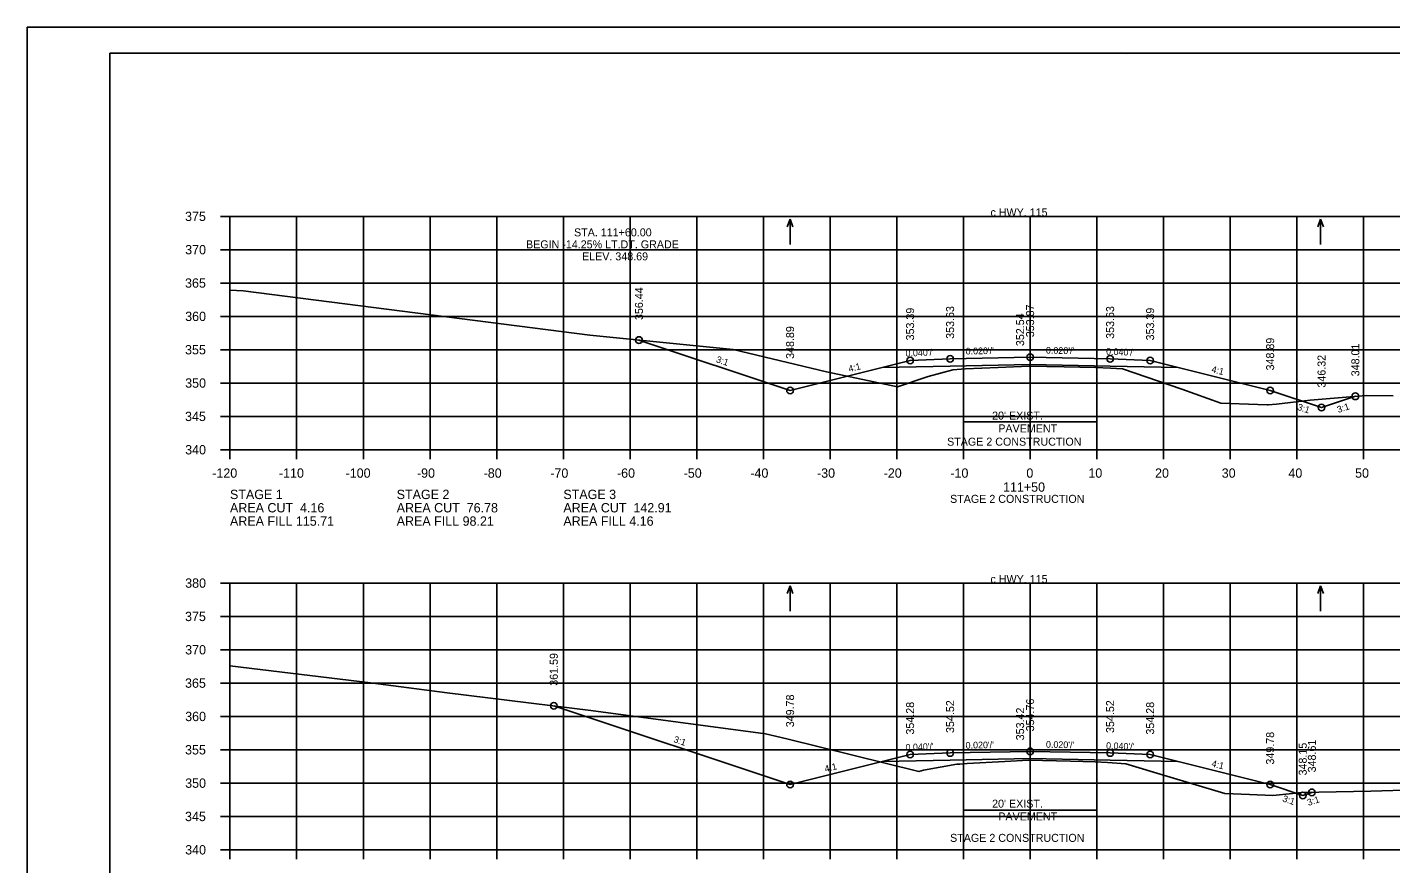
# Model space of a CAD drawing. Extents: x 1630712 to 1632516, y 782146 to 785403.
# Drawn here: x 1632182.6 to 1632387, y 784424.5 to 784550 of the extents above; entities that cross this region are included whole.
import ezdxf

# ---------------------------------------------------------------- set-up
doc = ezdxf.new("R2010")
doc.units = 0
for name, color, linetype in [('Notes', 7, 'Continuous'), ('R_Alt Surface', 7, 'Continuous'), ('R_Axis', 7, 'Continuous'), ('R_Axis Annot', 7, 'Continuous'), ('R_Border', 7, 'Continuous'), ('R_Exist Surface', 7, 'Continuous'), ('R_Fin Surface', 7, 'Continuous'), ('R_Grid', 7, 'Continuous'), ('R_No Plot', 7, 'Continuous'), ('R_Water Annot', 7, 'Continuous'), ('R_Xsect Elev', 7, 'Continuous'), ('R_Xsect Slope', 7, 'Continuous')]:
    doc.layers.add(name, color=color, linetype=linetype)

msp = doc.modelspace()

# ---------------------------------------------------------------- linework, layer by layer
at = {"layer": 'Notes'}
for p, q in [((1632322.96, 784489.09), (1632322.96, 784492.49)), ((1632322.96, 784490.79), (1632342.96, 784490.79)), ((1632342.96, 784489.09), (1632342.96, 784492.49)), ((1632322.96, 784430.89), (1632322.96, 784434.29)), ((1632342.96, 784430.89), (1632342.96, 784434.29)), ((1632322.96, 784432.59), (1632342.96, 784432.59))]:
    msp.add_line(p, q, dxfattribs=at)
at = {"layer": 'R_Alt Surface'}
for points in [[(1632310.78, 784498.97), (1632320.96, 784499.18), (1632332.96, 784499.42), (1632344.96, 784499.18), (1632355.15, 784498.97)], [(1632310.78, 784439.86), (1632320.96, 784440.07), (1632332.96, 784440.31), (1632344.96, 784440.07), (1632355.15, 784439.86)]]:
    msp.add_lwpolyline(points, dxfattribs=at)
at = {"layer": 'R_Axis'}
for p, q in [((1632211.56, 784521.63), (1632212.96, 784521.63)), ((1632212.96, 784486.63), (1632212.96, 784521.63)), ((1632211.56, 784516.63), (1632212.96, 784516.63)), ((1632211.56, 784511.63), (1632212.96, 784511.63)), ((1632211.56, 784506.63), (1632212.96, 784506.63)), ((1632211.56, 784501.63), (1632212.96, 784501.63)), ((1632211.56, 784496.63), (1632212.96, 784496.63)), ((1632211.56, 784491.63), (1632212.96, 784491.63)), ((1632211.56, 784486.63), (1632212.96, 784486.63)), ((1632212.96, 784486.63), (1632492.96, 784486.63)), ((1632212.96, 784485.23), (1632212.96, 784486.63)), ((1632222.96, 784485.23), (1632222.96, 784486.63)), ((1632232.96, 784485.23), (1632232.96, 784486.63)), ((1632242.96, 784485.23), (1632242.96, 784486.63)), ((1632252.96, 784485.23), (1632252.96, 784486.63)), ((1632262.96, 784485.23), (1632262.96, 784486.63)), ((1632272.96, 784485.23), (1632272.96, 784486.63)), ((1632282.96, 784485.23), (1632282.96, 784486.63)), ((1632292.96, 784485.23), (1632292.96, 784486.63)), ((1632302.96, 784485.23), (1632302.96, 784486.63)), ((1632312.96, 784485.23), (1632312.96, 784486.63)), ((1632322.96, 784485.23), (1632322.96, 784486.63)), ((1632332.96, 784485.23), (1632332.96, 784486.63)), ((1632342.96, 784485.23), (1632342.96, 784486.63)), ((1632352.96, 784485.23), (1632352.96, 784486.63)), ((1632362.96, 784485.23), (1632362.96, 784486.63)), ((1632372.96, 784485.23), (1632372.96, 784486.63)), ((1632382.96, 784485.23), (1632382.96, 784486.63)), ((1632211.56, 784466.63), (1632212.96, 784466.63)), ((1632212.96, 784426.63), (1632212.96, 784466.63)), ((1632211.56, 784461.63), (1632212.96, 784461.63)), ((1632211.56, 784456.63), (1632212.96, 784456.63)), ((1632211.56, 784451.63), (1632212.96, 784451.63)), ((1632211.56, 784446.63), (1632212.96, 784446.63)), ((1632211.56, 784441.63), (1632212.96, 784441.63)), ((1632211.56, 784436.63), (1632212.96, 784436.63)), ((1632211.56, 784431.63), (1632212.96, 784431.63)), ((1632211.56, 784426.63), (1632212.96, 784426.63)), ((1632212.96, 784426.63), (1632492.96, 784426.63)), ((1632212.96, 784425.23), (1632212.96, 784426.63)), ((1632222.96, 784425.23), (1632222.96, 784426.63)), ((1632232.96, 784425.23), (1632232.96, 784426.63)), ((1632242.96, 784425.23), (1632242.96, 784426.63)), ((1632252.96, 784425.23), (1632252.96, 784426.63)), ((1632262.96, 784425.23), (1632262.96, 784426.63)), ((1632272.96, 784425.23), (1632272.96, 784426.63)), ((1632282.96, 784425.23), (1632282.96, 784426.63)), ((1632292.96, 784425.23), (1632292.96, 784426.63)), ((1632302.96, 784425.23), (1632302.96, 784426.63)), ((1632312.96, 784425.23), (1632312.96, 784426.63)), ((1632322.96, 784425.23), (1632322.96, 784426.63)), ((1632332.96, 784425.23), (1632332.96, 784426.63)), ((1632342.96, 784425.23), (1632342.96, 784426.63)), ((1632352.96, 784425.23), (1632352.96, 784426.63)), ((1632362.96, 784425.23), (1632362.96, 784426.63)), ((1632372.96, 784425.23), (1632372.96, 784426.63)), ((1632382.96, 784425.23), (1632382.96, 784426.63))]:
    msp.add_line(p, q, dxfattribs=at)
at = {"layer": 'R_Border'}
for p, q in [((1632194.96, 784546.09), (1632511.14, 784546.09)), ((1632194.96, 784340.63), (1632194.96, 784546.09)), ((1632347.48, 784545.83), (1632347.48, 784545.83)), ((1632347.48, 784545.83), (1632347.48, 784545.83))]:
    msp.add_line(p, q, dxfattribs=at)
at = {"layer": 'R_Exist Surface'}
for points in [[(1632212.96, 784510.58), (1632214.92, 784510.44), (1632266.95, 784503.82), (1632288.42, 784501.64), (1632302.44, 784498.29), (1632313.05, 784496.07), (1632317.69, 784497.6), (1632321.36, 784498.59), (1632322.61, 784498.72), (1632323.29, 784498.77), (1632328.17, 784498.98), (1632332.8, 784499.17), (1632338.09, 784499.07), (1632342.77, 784498.98), (1632345.04, 784498.86), (1632346.8, 784498.78), (1632355.7, 784495.71), (1632361.57, 784493.59), (1632367.11, 784493.41), (1632368.51, 784493.37), (1632368.65, 784493.37), (1632369.92, 784493.47), (1632374.95, 784494.07), (1632383.37, 784494.78), (1632387.42, 784494.7)], [(1632212.96, 784454.2), (1632234.02, 784451.68), (1632245.51, 784450.19), (1632267.07, 784447.54), (1632293.29, 784444), (1632296.45, 784443.29), (1632316.27, 784438.39), (1632316.99, 784438.55), (1632321.99, 784439.45), (1632322.41, 784439.48), (1632323.53, 784439.59), (1632329.19, 784439.88), (1632332.7, 784440.05), (1632339.02, 784439.91), (1632342.72, 784439.83), (1632344.58, 784439.72), (1632347.31, 784439.53), (1632353.47, 784437.67), (1632362.15, 784435.06), (1632365.87, 784434.93), (1632369.38, 784434.78), (1632372.3, 784435.08), (1632373.68, 784435.21), (1632384.07, 784435.42), (1632397.36, 784435.83)]]:
    msp.add_lwpolyline(points, dxfattribs=at)
at = {"layer": 'R_Fin Surface'}
for points in [[(1632274.3, 784503.08), (1632296.96, 784495.52), (1632310.78, 784498.97), (1632314.96, 784500.02), (1632320.96, 784500.26), (1632332.96, 784500.5), (1632344.96, 784500.26), (1632350.96, 784500.02), (1632355.15, 784498.97), (1632368.96, 784495.52), (1632376.67, 784492.95), (1632381.74, 784494.64)], [(1632261.52, 784448.23), (1632296.96, 784436.41), (1632310.78, 784439.86), (1632314.96, 784440.91), (1632320.96, 784441.15), (1632332.96, 784441.39), (1632344.96, 784441.15), (1632350.96, 784440.91), (1632355.15, 784439.86), (1632368.96, 784436.41), (1632373.85, 784434.78), (1632375.22, 784435.24)]]:
    msp.add_lwpolyline(points, dxfattribs=at)
at = {"layer": 'R_Grid'}
for p, q in [((1632212.96, 784521.63), (1632492.96, 784521.63)), ((1632212.96, 784486.63), (1632212.96, 784521.63)), ((1632222.96, 784486.63), (1632222.96, 784521.63)), ((1632232.96, 784486.63), (1632232.96, 784521.63)), ((1632242.96, 784486.63), (1632242.96, 784521.63)), ((1632252.96, 784486.63), (1632252.96, 784521.63)), ((1632262.96, 784486.63), (1632262.96, 784521.63)), ((1632272.96, 784486.63), (1632272.96, 784521.63)), ((1632282.96, 784486.63), (1632282.96, 784521.63)), ((1632292.96, 784486.63), (1632292.96, 784521.63)), ((1632302.96, 784486.63), (1632302.96, 784521.63)), ((1632312.96, 784486.63), (1632312.96, 784521.63)), ((1632322.96, 784486.63), (1632322.96, 784521.63)), ((1632332.96, 784486.63), (1632332.96, 784521.63)), ((1632342.96, 784486.63), (1632342.96, 784521.63)), ((1632352.96, 784486.63), (1632352.96, 784521.63)), ((1632362.96, 784486.63), (1632362.96, 784521.63)), ((1632372.96, 784486.63), (1632372.96, 784521.63)), ((1632382.96, 784486.63), (1632382.96, 784521.63)), ((1632212.96, 784516.63), (1632492.96, 784516.63)), ((1632212.96, 784511.63), (1632492.96, 784511.63)), ((1632212.96, 784506.63), (1632492.96, 784506.63)), ((1632212.96, 784501.63), (1632492.96, 784501.63)), ((1632212.96, 784496.63), (1632492.96, 784496.63)), ((1632212.96, 784491.63), (1632492.96, 784491.63)), ((1632212.96, 784486.63), (1632492.96, 784486.63)), ((1632212.96, 784466.63), (1632492.96, 784466.63)), ((1632212.96, 784426.63), (1632212.96, 784466.63)), ((1632222.96, 784426.63), (1632222.96, 784466.63)), ((1632232.96, 784426.63), (1632232.96, 784466.63)), ((1632242.96, 784426.63), (1632242.96, 784466.63)), ((1632252.96, 784426.63), (1632252.96, 784466.63)), ((1632262.96, 784426.63), (1632262.96, 784466.63)), ((1632272.96, 784426.63), (1632272.96, 784466.63)), ((1632282.96, 784426.63), (1632282.96, 784466.63)), ((1632292.96, 784426.63), (1632292.96, 784466.63)), ((1632302.96, 784426.63), (1632302.96, 784466.63)), ((1632312.96, 784426.63), (1632312.96, 784466.63)), ((1632322.96, 784426.63), (1632322.96, 784466.63)), ((1632332.96, 784426.63), (1632332.96, 784466.63)), ((1632342.96, 784426.63), (1632342.96, 784466.63)), ((1632352.96, 784426.63), (1632352.96, 784466.63)), ((1632362.96, 784426.63), (1632362.96, 784466.63)), ((1632372.96, 784426.63), (1632372.96, 784466.63)), ((1632382.96, 784426.63), (1632382.96, 784466.63)), ((1632212.96, 784461.63), (1632492.96, 784461.63)), ((1632212.96, 784456.63), (1632492.96, 784456.63)), ((1632212.96, 784451.63), (1632492.96, 784451.63)), ((1632212.96, 784446.63), (1632492.96, 784446.63)), ((1632212.96, 784441.63), (1632492.96, 784441.63)), ((1632212.96, 784436.63), (1632492.96, 784436.63)), ((1632212.96, 784431.63), (1632492.96, 784431.63)), ((1632212.96, 784426.63), (1632492.96, 784426.63))]:
    msp.add_line(p, q, dxfattribs=at)
at = {"layer": 'R_No Plot'}
msp.add_line((1632182.56, 784549.99), (1632515.9, 784549.99), dxfattribs=at)
msp.add_lwpolyline([(1632182.56, 784549.99), (1632515.9, 784549.99), (1632515.9, 784336.65), (1632182.56, 784336.65)], close=True, dxfattribs=at)
for centre in [(1632274.3, 784503.08), (1632320.96, 784500.26), (1632332.96, 784500.5), (1632344.96, 784500.26), (1632314.96, 784500.02), (1632350.96, 784500.02), (1632296.96, 784495.52), (1632296.96, 784495.52), (1632368.96, 784495.52), (1632381.74, 784494.64), (1632376.67, 784492.95), (1632261.52, 784448.23), (1632320.96, 784441.15), (1632332.96, 784441.39), (1632344.96, 784441.15), (1632314.96, 784440.91), (1632350.96, 784440.91), (1632296.96, 784436.41), (1632296.96, 784436.41), (1632368.96, 784436.41), (1632375.22, 784435.24), (1632373.85, 784434.78)]:
    msp.add_circle(centre, 0.5, dxfattribs=at)
at = {"layer": 'R_Water Annot'}
for p, q in [((1632296.96, 784521.2), (1632296.54, 784520.05)), ((1632296.96, 784517.43), (1632296.96, 784521.2)), ((1632296.96, 784521.2), (1632297.38, 784520.05)), ((1632376.53, 784521.2), (1632376.11, 784520.05)), ((1632376.53, 784517.43), (1632376.53, 784521.2)), ((1632376.53, 784521.2), (1632376.95, 784520.05)), ((1632296.96, 784466.2), (1632296.54, 784465.05)), ((1632296.96, 784462.43), (1632296.96, 784466.2)), ((1632296.96, 784466.2), (1632297.38, 784465.05)), ((1632376.53, 784466.2), (1632376.11, 784465.05)), ((1632376.53, 784462.43), (1632376.53, 784466.2)), ((1632376.53, 784466.2), (1632376.95, 784465.05))]:
    msp.add_line(p, q, dxfattribs=at)

# ---------------------------------------------------------------- texts
at = {"layer": 'Notes'}
for s, p in [('c HWY. 115', (1632327.02, 784521.63)), ('STA. 111+60.00', (1632264.56, 784518.63)), ('BEGIN -14.25% LT.DT. GRADE', (1632257.36, 784516.83)), ('ELEV. 348.69', (1632265.76, 784515.03)), ("20' EXIST.", (1632327.26, 784491.15)), ('PAVEMENT', (1632328.19, 784489.23)), ('STAGE 2 CONSTRUCTION', (1632320.51, 784487.24)), ('STAGE 2 CONSTRUCTION', (1632320.96, 784478.66)), ('c HWY. 115', (1632327.02, 784466.63)), ("20' EXIST.", (1632327.26, 784432.95)), ('PAVEMENT', (1632328.19, 784431.03)), ('STAGE 2 CONSTRUCTION', (1632320.96, 784427.82))]:
    msp.add_text(s, height=1.2, dxfattribs=at).set_placement(p)
at = {"layer": 'R_Axis'}
for p in [(1632212.96, 784486.63), (1632212.96, 784426.63)]:
    msp.add_text('-', height=0.0001, dxfattribs=at).set_placement(p)
at = {"layer": 'R_Axis Annot'}
for s, p in [('375', (1632206.22, 784520.93)), ('370', (1632206.24, 784515.93)), ('365', (1632206.22, 784510.93)), ('360', (1632206.24, 784505.93)), ('355', (1632206.22, 784500.93)), ('350', (1632206.24, 784495.93)), ('345', (1632206.22, 784490.93)), ('340', (1632206.24, 784485.93)), ('-120', (1632210.3, 784482.43)), ('-110', (1632220.3, 784482.43)), ('-100', (1632230.3, 784482.43)), ('-90', (1632241, 784482.43)), ('-80', (1632251, 784482.43)), ('-70', (1632261, 784482.43)), ('-60', (1632271, 784482.43)), ('-50', (1632281, 784482.43)), ('-40', (1632291, 784482.43)), ('-30', (1632301, 784482.43)), ('-20', (1632311, 784482.43)), ('-10', (1632321, 784482.43)), ('0', (1632332.4, 784482.43)), ('10', (1632341.7, 784482.43)), ('20', (1632351.7, 784482.43)), ('30', (1632361.7, 784482.43)), ('40', (1632371.7, 784482.43)), ('50', (1632381.7, 784482.43)), ('STAGE 1', (1632212.96, 784479.23)), ('STAGE 2', (1632237.96, 784479.23)), ('STAGE 3', (1632262.96, 784479.23)), ('111+50', (1632328.9, 784480.33)), ('AREA CUT  4.16', (1632212.96, 784477.23)), ('AREA CUT  76.78', (1632237.96, 784477.23)), ('AREA CUT  142.91', (1632262.96, 784477.23)), ('AREA FILL 115.71', (1632212.96, 784475.23)), ('AREA FILL 98.21', (1632237.96, 784475.23)), ('AREA FILL 4.16', (1632262.96, 784475.23)), ('380', (1632206.24, 784465.93)), ('375', (1632206.22, 784460.93)), ('370', (1632206.24, 784455.93)), ('365', (1632206.22, 784450.93)), ('360', (1632206.24, 784445.93)), ('355', (1632206.22, 784440.93)), ('350', (1632206.24, 784435.93)), ('345', (1632206.22, 784430.93)), ('340', (1632206.24, 784425.93))]:
    msp.add_text(s, height=1.4, dxfattribs=at).set_placement(p)
at = {"layer": 'R_Xsect Elev'}
for s, p in [('356.44', (1632274.9, 784506.08)), ('353.39', (1632315.56, 784503.02)), ('353.63', (1632321.56, 784503.26)), ('352.54', (1632332.06, 784502.17)), ('353.87', (1632333.56, 784503.5)), ('353.63', (1632345.56, 784503.26)), ('353.39', (1632351.56, 784503.02)), ('348.89', (1632297.56, 784500.25)), ('348.89', (1632369.56, 784498.52)), ('346.32', (1632377.27, 784495.95)), ('348.01', (1632382.34, 784497.64)), ('361.59', (1632262.12, 784451.23)), ('349.78', (1632297.56, 784445.01)), ('354.28', (1632315.56, 784443.91)), ('354.52', (1632321.56, 784444.15)), ('353.42', (1632332.06, 784443.05)), ('354.76', (1632333.56, 784444.39)), ('354.52', (1632345.56, 784444.15)), ('354.28', (1632351.56, 784443.91)), ('349.78', (1632369.56, 784439.41)), ('348.15', (1632374.45, 784437.78)), ('348.61', (1632375.82, 784438.24))]:
    msp.add_text(s, height=1.2, rotation=90, dxfattribs=at).set_placement(p)
at = {"layer": 'R_Xsect Slope'}
for s, rotation, p in [("0.040'/'", 2.2906, (1632314.29, 784500.59)), ("0.020'/'", 1.1458, (1632323.3, 784500.91)), ("0.020'/'", 358.8542, (1632335.33, 784501.05)), ("0.040'/'", 357.7094, (1632344.34, 784500.89)), ('3:1', 341.5651, (1632285.79, 784499.77)), ('4:1', 14.0362, (1632305.84, 784498.26)), ('4:1', 345.9638, (1632360.09, 784498.26)), ('3:1', 341.5651, (1632372.95, 784492.64)), ('3:1', 18.4349, (1632379.19, 784492.13)), ('3:1', 341.5651, (1632279.4, 784442.79)), ("0.040'/'", 2.2906, (1632314.29, 784441.48)), ("0.020'/'", 1.1458, (1632323.3, 784441.8)), ("0.020'/'", 358.8542, (1632335.33, 784441.94)), ("0.040'/'", 357.7094, (1632344.34, 784441.78)), ('4:1', 14.0362, (1632302.26, 784438.26)), ('4:1', 345.9638, (1632360.09, 784439.14)), ('3:1', 341.5651, (1632370.72, 784433.91)), ('3:1', 18.4349, (1632374.71, 784433.2))]:
    msp.add_text(s, height=1, rotation=rotation, dxfattribs=at).set_placement(p)

doc.saveas('drawing.dxf')
